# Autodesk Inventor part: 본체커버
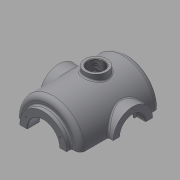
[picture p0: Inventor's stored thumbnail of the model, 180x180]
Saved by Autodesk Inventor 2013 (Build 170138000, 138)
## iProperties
Created: 2016-02
Part Number: 본체커버
Material: 알루미늄 6061
Document SubType Name: Modeling
Designer: mduedu
Density: 2.71 g/cm^3
Mass: 1187.08 g
Surface Area: 904.866 cm^2
Volume: 438.037 cm^3
Author: mduedu
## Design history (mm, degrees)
sketch "스케치2"
  geometry: L1 (0, 90)-(0, -90); L2 (65, -65.993)-(65, 90); L3 (65, 90)-(0, 90); A1 r 100 centre (0, 10) between (0, -90) and (65, -65.993); 2 further points
  constraints: 6 end point, 2 point on circle, 1 centre point, 1 coincident, 1 horizontal, 1 midpoint, 1 parallel, 1 point on line, 1 vertical
  dimensions: "d3" = 180 distance of L1.start L1.end; "d5" = 130 diameter of L2 L1; "d6" = 100 radius of A1
revolve "회전1" sketch "스케치2" stored, may be unused: angle "d7" = 90 deg
sketch "스케치3"
  geometry: C1 r 47.5 at (0, 0); 1 further point
  constraints: 1 centre point, 1 coincident
  dimensions: "d8" = 95 diameter of C1
extrude "돌출2" join sketch "스케치3" distance "d10" = 10; taper "d11" = 0 deg
sketch "스케치5"
  geometry: L1 (47.5, 100)-(47.5, 90) reference; L2 (47.5, 90)-(65, 90) reference; L3 (65, 90)-(65, -65.993) reference; L4 (-65, -65.993)-(-65, 90) reference; L5 (-65, 90)-(-47.5, 90) reference; L6 (-47.5, 90)-(-47.5, 100) reference; L7 (-47.5, 100)-(47.5, 100) reference; L8 (55, 75)-(55, -61.239); L9 (0, 75)-(55, 75); L10 (0, 75)-(0, -80); A1 r 100 centre (0, 10) between (-65, -65.993) and (0, -90) reference; A2 r 100 centre (0, 10) between (0, -90) and (65, -65.993) reference; A3 r 90 centre (0, 10) between (0, -80) and (55, -61.239); 1 further point
  constraints: 6 end point, 2 point on circle, 1 centre point, 1 parallel, 1 perpendicular, 1 point on line, 1 vertical
  dimensions: "d13" = 10 distance between parallel lines of L3 L8; "d14" = 10 radial gap between concentric circles of A3 A1; "d15" = 15 distance between parallel lines of L9 L2
revolve "회전2" sketch "스케치5" stored, may be unused: angle "d16" = 90 deg
hole "구멍1" diameter "d19" = 65; stored, may be unused: countersink angle "d23" = 90 deg, drill point angle "d25" = 118 deg; dims "d17" = 10, "d18" = 10, "d20" = 6, "d21" = 4, "d22" = 2, "d24" = 8
node "작업 평면1"
sketch "스케치6"
  geometry: L1 (47.5, 100)-(-47.5, 100) reference; C1 r 40 at (0, -7); 1 further point
  constraints: 1 centre point, 1 vertical alignment
  dimensions: "d27" = 80 diameter of C1; "d29" = 107 distance from line of C1.centre L1
extrude "돌출3" join sketch "스케치6" stored distance "d30" = 10; taper "d31" = 0 deg
hole "구멍2" diameter "d34" = 42; stored, may be unused: countersink angle "d38" = 90 deg, drill point angle "d40" = 118 deg; dims "d32" = 10, "d33" = 10, "d35" = 6, "d36" = 52, "d37" = 18, "d39" = 8
sketch "스케치7" dims "d41" = 65
  geometry: C1 r 40 at (0, 0) reference; 3 further points
  constraints: 2 vertical alignment, 1 coincident, 2 other
hole "구멍3" sketch "스케치7" at (0, 32.5) diameter "d43" = 3.242; stored, may be unused: countersink angle "d47" = 90 deg, drill point angle "d49" = 118 deg; dims "d44" = 11, "d45" = 13, "d46" = 18, "d48" = 13
sketch "스케치8" dims "d53" = 80
  geometry: 3 further points
  constraints: 2 vertical alignment, 1 coincident, 2 other
hole "구멍4" sketch "스케치8" at (0, -40) diameter "d56" = 3.242; stored, may be unused: countersink angle "d60" = 90 deg, drill point angle "d62" = 118 deg; dims "d57" = 11, "d58" = 13, "d59" = 18, "d61" = 13
fillet "모깎기1" dims "d66" = 10
fillet "모깎기2" dims "d67" = 3
fillet "모깎기3" dims "d68" = 0.3
chamfer "모따기1" distance "d69" = 1; stored, may be unused: second distance "d70" = 2, angle "d71" = 45 deg
node "작업 평면5"
sketch "스케치10"
  geometry: L1 (-50, 66)-(50, 66); L2 (50, 66)-(50, 50); L3 (50, 50)-(-50, 50); L4 (-50, 50)-(-50, 66); 2 further points
  constraints: 8 end point, 2 horizontal, 2 vertical, 1 midpoint, 1 vertical alignment
  dimensions: "d177" = 50 distance from line of L3 point (0, 0); "d178" = 100 distance of L1.start L1.end; "d179" = 16 distance of L3.end L1.start
extrude "돌출5" join sketch "스케치10" stored distance "d84" = 10; taper "d85" = 0 deg
sketch "스케치21" dims "d180" = 220, "d182" = 130
  geometry: L1 (65, 58)-(-65, 58); L2 (-65, 58)-(-65, -32); L3 (-65, -32)-(65, -32); L4 (65, -32)-(65, 58); L5 (50, 50)-(50, 66) reference; 4 further points
  constraints: 8 end point, 3 horizontal alignment, 3 midpoint, 2 parallel, 1 horizontal, 1 perpendicular, 1 vertical alignment, 4 other
extrude "돌출13" join sketch "스케치21" distance "d183" = 10; taper "d184" = 0 deg
sketch "스케치11"
  geometry: L1 (-65, 80)-(-65, -61.239) reference; L2 (-100, -97)-(-100, -32) reference; L3 (-65, -42.793)-(-100, -63); L4 (-100, -97)-(-110, -97) reference; 1 further point
  constraints: 2 end point, 2 point on line
  dimensions: "d185" = 34 distance from line of L3.end L4; "d186" = 120 deg angle of L2 L3
feature "리브1" sketch "스케치11" dims "d88" = 1, "d89" = 16, "d90" = 0, "d91" = 0, "d92" = 1, "d93" = 1
fillet "모깎기12"
fillet "모깎기13"
fillet "모깎기16" dims "d167" = 3
fillet "모깎기18"
fillet "모깎기17" dims "d168" = 3
fillet "모깎기19" dims "d187" = 3
node "작업 평면6"
sketch "스케치19"
  geometry: L1 (75, -47)-(75, 33) reference; L2 (-75, -47)-(-75, 33) reference; L3 (75, -7)-(-75, -7); C1 r 22.5 at (0, -7); 1 further point
  constraints: 3 midpoint, 2 end point, 1 centre point
  dimensions: "d149" = 45 diameter of C1
extrude "돌출11" join sketch "스케치19" stored distance "d150" = 10; taper "d151" = 0 deg
hole "구멍6" diameter "d154" = 33.376; stored, may be unused: countersink angle "d158" = 90 deg, drill point angle "d160" = 118 deg; dims "d155" = 6, "d156" = 4, "d157" = 2, "d159" = 8, "d190" = 10, "d191" = 10
fillet "모깎기11" dims "d161" = 3
chamfer "모따기3" distance "d164" = 1; stored, may be unused: second distance "d165" = 2, angle "d166" = 45 deg
sketch "스케치22" dims "d189" = 20
  geometry: L1 (-10, -123)-(10, -123); L2 (10, -123)-(10, -103); L3 (10, -103)-(-10, -103); L4 (-10, -103)-(-10, -123); A1 r 65 centre (0, -58) between (-65, -58) and (65, -58) reference; 2 further points
  constraints: 8 end point, 2 parallel, 1 horizontal, 1 horizontal alignment, 1 midpoint, 1 perpendicular, 1 tangent, 1 vertical alignment, 2 other
  dimensions: "d193" = 30 dimension on L1
extrude "돌출14" cut sketch "스케치22" stored distance "d194" = 10; taper "d195" = 0 deg
fillet "모깎기21" dims "d196" = 3
feature "분할1"
node "솔리드2"
pattern_circular "원형 패턴1" dims angle "d51" = 360 deg
mirror "대칭1"
pattern_circular "원형 패턴2" dims angle "d64" = 360 deg
node "절단 모서리 투영1"
other parameters: "d26" = 75, "d136" = 175
